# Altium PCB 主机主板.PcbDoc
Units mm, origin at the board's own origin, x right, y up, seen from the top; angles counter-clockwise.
Board outline 20.02 x 52.05 mm, 2 copper layers (Top Layer, Bottom Layer), stack 1.793 mm thick; 21 components, 30 nets, 89 pads, 104 vias.
Unrouted connection lines stored in the file: 27.
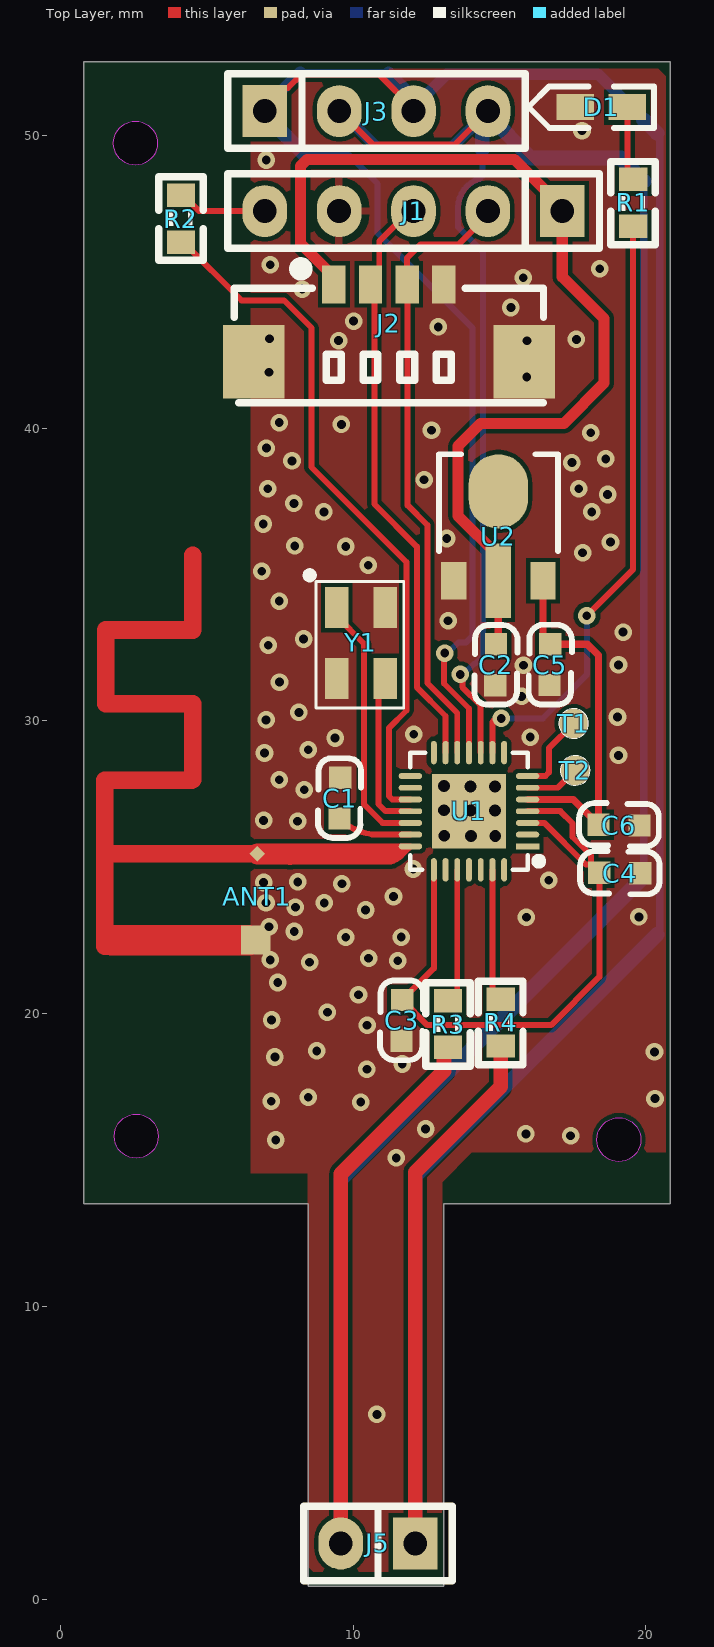
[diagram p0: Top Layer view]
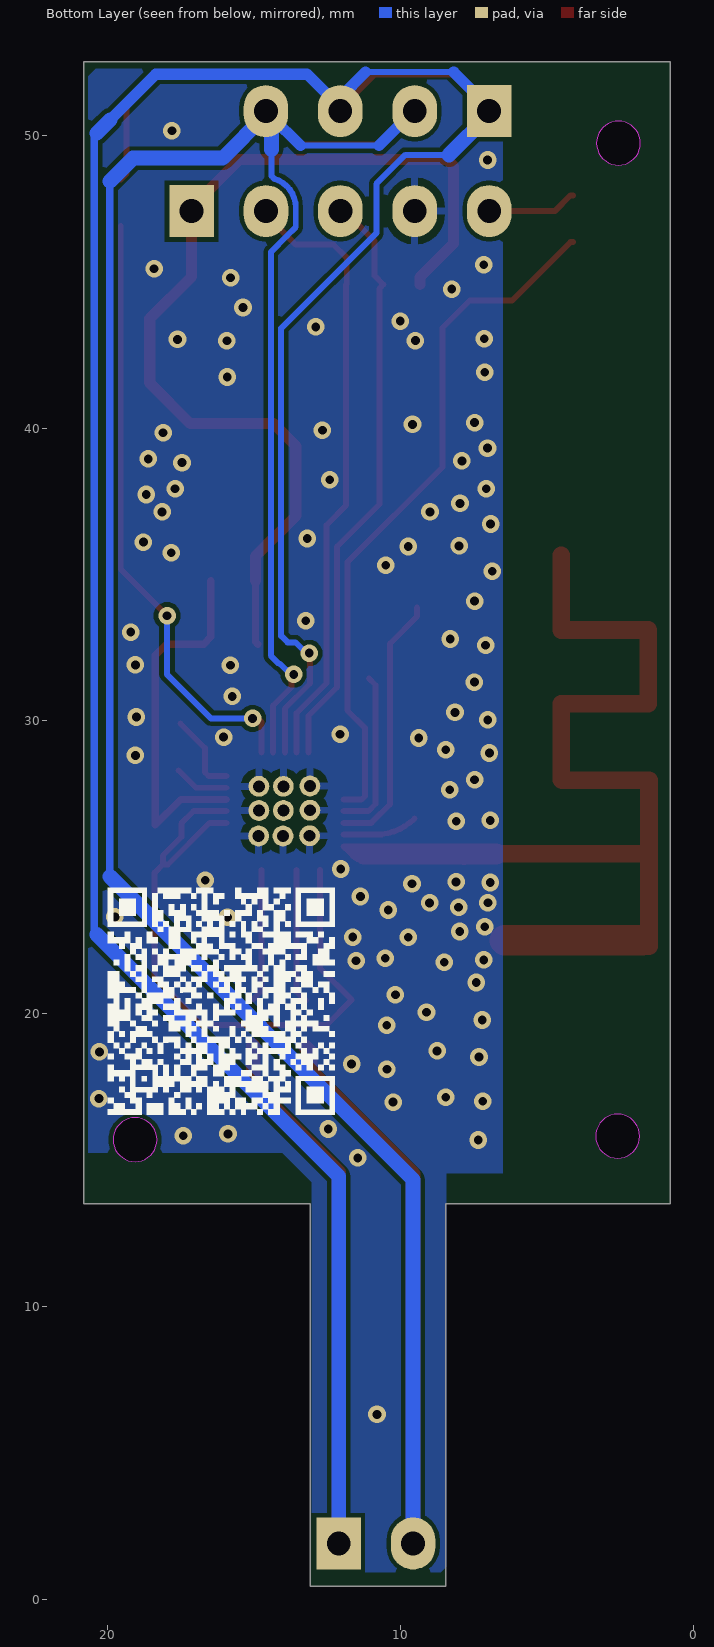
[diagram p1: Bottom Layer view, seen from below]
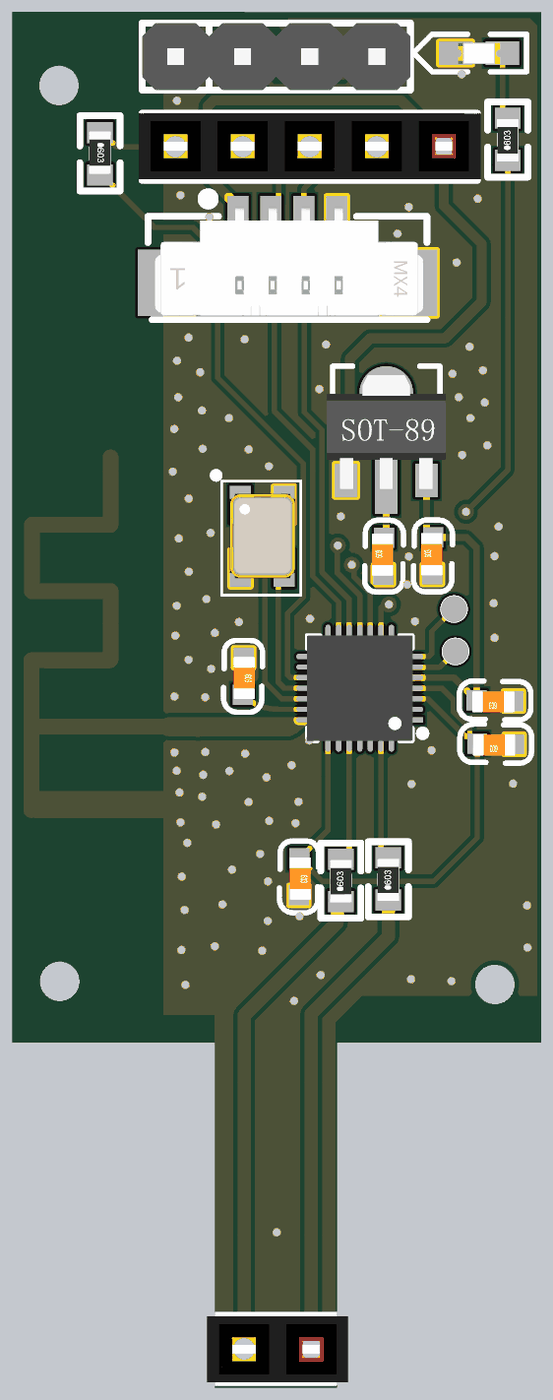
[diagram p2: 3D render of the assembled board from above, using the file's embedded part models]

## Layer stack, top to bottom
Top Solder: solder mask 0.0102, Solder Resist, Dk 3.5
Top Layer: signal copper 0.0356
Dielectric 2: prepreg 0.0508, FR-4, Dk 4.61
Dielectric 1: prepreg 1.62, FR-4, Dk 4.61
Dielectric 3: prepreg 0.0508, FR-4, Dk 4.61
Bottom Layer: signal copper 0.0356
Bottom Solder: solder mask 0.0102, Solder Resist, Dk 3.5

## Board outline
0.807,13.509 0.807,52.505 0.813,52.502 20.827,52.502 20.827,13.509 13.091,13.509 13.091,0.457 8.476,0.457 8.476,13.509
cut-out: 19.076,14.956 cw(c19.076,15.706) 18.326,15.706 cw(c19.076,15.706) 19.076,16.456 cw(c19.076,15.706) 19.826,15.706 cw(c19.076,15.706)
cut-out: 2.599,15.075 cw(c2.599,15.825) 1.849,15.825 cw(c2.599,15.825) 2.599,16.575 cw(c2.599,15.825) 3.349,15.825 cw(c2.599,15.825)
cut-out: 2.572,48.975 cw(c2.572,49.725) 1.822,49.725 cw(c2.572,49.725) 2.572,50.475 cw(c2.572,49.725) 3.322,49.725 cw(c2.572,49.725)

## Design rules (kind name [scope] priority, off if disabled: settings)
Clearance [All] p1: gap=0.152 ignorepadtopadclearanceinfootprint=FALSE
Height [All] p1: minheight=0 maxheight=254 prefheight=12.7
HoleSize [All] p1: absolutevalues=TRUE maxlimit=5.08 minlimit=0.025 maxpercent=80.000 minpercent=20.000
HoleToHoleClearance [All] p1: gap=0.36 allowstackedmicrovias=TRUE
MinimumSolderMaskSliver [All] p1: minsoldermaskwidth=0
PlaneConnect [All] p1: planeconnectstyle=Relief reliefexpansion=0.254 reliefentries=4 reliefconductorwidth=0.102 reliefairgap=0.127
PolygonConnect PolygonConnect_9 [All vs IsNamedPolygon('Top Layer-GND')] p1: connectstyle=Direct reliefconductorwidth=0.254 reliefentries=4 polygonreliefangle="90 Angle" airgapwidth=0.254
PolygonConnect PolygonConnect_8 [All vs IsNamedPolygon('Bottom Layer-GND')] p2: connectstyle=Direct reliefconductorwidth=0.254 reliefentries=4 polygonreliefangle="90 Angle" airgapwidth=0.254
PolygonConnect PolygonConnect_7 [All vs IsNamedPolygon('Bottom Layer-GND')] p3: thpad.connectstyle=Direct thpad.reliefconductorwidth=0.254 thpad.reliefentries=4 thpad.polygonreliefangle="90 Angle" thpad.airgapwidth=0.254 smdpad.connectstyle=Direct smdpad.reliefconductorwidth=0.254 smdpad.reliefentries=4 smdpad.polygonreliefangle="90 Angle" smdpad.airgapwidth=0.254 via.connectstyle=Relief via.reliefconductorwidth=0.254 via.reliefentries=4 via.polygonreliefangle="90 Angle" via.airgapwidth=0.254
PolygonConnect PolygonConnect_6 [All vs IsNamedPolygon('Top Layer-GND')] p4: thpad.connectstyle=Direct thpad.reliefconductorwidth=0.254 thpad.reliefentries=4 thpad.polygonreliefangle="90 Angle" thpad.airgapwidth=0.254 smdpad.connectstyle=Direct smdpad.reliefconductorwidth=0.254 smdpad.reliefentries=4 smdpad.polygonreliefangle="90 Angle" smdpad.airgapwidth=0.254 via.connectstyle=Relief via.reliefconductorwidth=0.254 via.reliefentries=4 via.polygonreliefangle="90 Angle" via.airgapwidth=0.254
PolygonConnect PolygonConnect_5 [All vs IsNamedPolygon('Top Layer-GND')] p5: thpad.connectstyle=Relief thpad.reliefconductorwidth=0.254 thpad.reliefentries=4 thpad.polygonreliefangle="90 Angle" thpad.airgapwidth=0.254 smdpad.connectstyle=Direct smdpad.reliefconductorwidth=0.254 smdpad.reliefentries=4 smdpad.polygonreliefangle="90 Angle" smdpad.airgapwidth=0.254 via.connectstyle=Relief via.reliefconductorwidth=0.254 via.reliefentries=4 via.polygonreliefangle="90 Angle" via.airgapwidth=0.254
PolygonConnect PolygonConnect_4 [All vs IsNamedPolygon('NONET_L-01_P-001')] p6: thpad.connectstyle=Relief thpad.reliefconductorwidth=0.254 thpad.reliefentries=4 thpad.polygonreliefangle="90 Angle" thpad.airgapwidth=0.254 smdpad.connectstyle=Direct smdpad.reliefconductorwidth=0.254 smdpad.reliefentries=4 smdpad.polygonreliefangle="90 Angle" smdpad.airgapwidth=0.254 via.connectstyle=Direct via.reliefconductorwidth=0.254 via.reliefentries=4 via.polygonreliefangle="90 Angle" via.airgapwidth=0.254
PolygonConnect PolygonConnect_3 [All vs IsNamedPolygon('NONET_L-01_P-001')] p7: thpad.connectstyle=Relief thpad.reliefconductorwidth=0.254 thpad.reliefentries=4 thpad.polygonreliefangle="90 Angle" thpad.airgapwidth=0.254 smdpad.connectstyle=Direct smdpad.reliefconductorwidth=0.254 smdpad.reliefentries=4 smdpad.polygonreliefangle="90 Angle" smdpad.airgapwidth=0.254 via.connectstyle=Direct via.reliefconductorwidth=0.254 via.reliefentries=4 via.polygonreliefangle="90 Angle" via.airgapwidth=0.254
PolygonConnect PolygonConnect_2 [All vs IsNamedPolygon('GND_L02_P001')] p8: thpad.connectstyle=Relief thpad.reliefconductorwidth=0.254 thpad.reliefentries=4 thpad.polygonreliefangle="90 Angle" thpad.airgapwidth=0.254 smdpad.connectstyle=Direct smdpad.reliefconductorwidth=0.254 smdpad.reliefentries=4 smdpad.polygonreliefangle="90 Angle" smdpad.airgapwidth=0.254 via.connectstyle=Direct via.reliefconductorwidth=0.254 via.reliefentries=4 via.polygonreliefangle="90 Angle" via.airgapwidth=0.254
PolygonConnect [All vs IsNamedPolygon('GND_L01_P002')] p9: thpad.connectstyle=Relief thpad.reliefconductorwidth=0.254 thpad.reliefentries=4 thpad.polygonreliefangle="90 Angle" thpad.airgapwidth=0.254 smdpad.connectstyle=Direct smdpad.reliefconductorwidth=0.254 smdpad.reliefentries=4 smdpad.polygonreliefangle="90 Angle" smdpad.airgapwidth=0.254 via.connectstyle=Direct via.reliefconductorwidth=0.254 via.reliefentries=4 via.polygonreliefangle="90 Angle" via.airgapwidth=0.254
PolygonConnect PolygonConnect_1 [All] p10: thpad.connectstyle=Relief thpad.reliefconductorwidth=0.254 thpad.reliefentries=4 thpad.polygonreliefangle="90 Angle" thpad.airgapwidth=0.254 smdpad.connectstyle=Relief smdpad.reliefconductorwidth=0.254 smdpad.reliefentries=4 smdpad.polygonreliefangle="90 Angle" smdpad.airgapwidth=0.152 via.connectstyle=Direct via.reliefconductorwidth=0.254 via.reliefentries=4 via.polygonreliefangle="45 Angle" via.airgapwidth=0.254
RoutingVias [All] p1: holewidth=0.3 width=0.3 viastyle="Through Hole" minholewidth=0.3 minwidth=0.3 maxholewidth=0.711 maxwidth=1.27
SilkToSilkClearance [All] p1: silktosilkclearance=0
SilkToSolderMaskClearance [IsPad] p1: minsilkscreentomaskgap=0 clearancetoexposedcopper=TRUE
SolderMaskExpansion [All] p1: expansion=0.102 istentingtop=FALSE
Width [All] p1: maxlimit=127 minlimit=0.076 preferedwidth=0.152
23 further rules are at their usual default settings.

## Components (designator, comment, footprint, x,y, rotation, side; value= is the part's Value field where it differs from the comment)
ANT1 "PCB ANT" ANT_2.4G_Pcb_ESP_C3_7P 6.505,22.566 r270 top
C1 "105" CAP_0603 9.572,27.357 r270 top
C2 "C0603" CAP_0603 14.847,31.924 r90 top value=105
C3 "104" CAP_0603 11.688,19.769 r270 top
C4 "105" CAP_0603 19.099,24.786 r180 top
C5 "105" CAP_0603 16.7,31.931 r90 top
C6 "C0603" CAP_0603 19.073,26.422 r180 top value=105
D1 "LED 正贴蓝灯" LED-0603W 19.364,50.958 r180 top
J1 "Female HDR1X5" Fe-HDR1X5/2.54-S 17.146,47.405 r270 top
J2 "MX1.25-4P" MX1.25S-4P 11.236,42.639 r0 top
J3 "Pin HDR1X4" "Pin HDR1X4/2.54mm-S" 6.988,50.818 r90 top
J5 "Female HDR1X2" Fe-HDR1X2/2.54-S 12.123,1.92 r180 top
R1 "R0603" RES_0603 19.563,47.677 r90 top value=1K
R2 "R0603" RES_0603 4.125,47.157 r270 top value=4.7K
R3 "R0603" RES_0603 13.243,19.64 r90 top value=4.7K
R4 "R0603" RES_0603 15.042,19.688 r90 top value=4.7K
T1 "TP" TEST 17.53,29.912 r0 top
T2 "TP" TEST 17.585,28.309 r0 top
U1 "CH573F" QFN28_4X4 15.959,25.718 r90 top
U2 "MD7530H" SOT89 14.962,34.786 r0 top
Y1 "XTAL3225" XT_3225_4 10.269,32.661 r270 top value="32MHz 10PPM 12PF"

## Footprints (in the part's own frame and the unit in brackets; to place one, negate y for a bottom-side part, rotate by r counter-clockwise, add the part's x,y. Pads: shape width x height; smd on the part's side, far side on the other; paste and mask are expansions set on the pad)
ANT_2.4G_Pcb_ESP_C3_7P [mm] "7P天线"
  rect 0.381x0.381 smd rot 135 paste-50.8 mask+0.102: 1(-2.893,0.227)
  rect 1x1 smd paste-50.8 mask+0.102: 2(0.043,0.172)
  Top Layer lines w0.6: 0.257,-4.977 -0.023,-4.977 ; -0.15,-4.977 -2.893,-4.977 ; -7.991,-1.98 -5.433,-1.98 -5.407,-2.005 -5.408,-4.977 -2.893,-4.977 ; -8.024,-1.98 -8.024,-4.951 -10.538,-4.951 -10.538,-1.98 -13.084,-1.98 ; -2.893,0.227 -2.893,0.194 -2.893,-0.265 -2.893,-4.977
  Top Layer lines w1.032: 0.053,-4.752 0.053,-0.053
CAP_0603 [mil]
  rect 30x30 smd: 1(-27.79,-0.35) 2(27.21,-1.35)
  silkscreen extent -54,-30 53,28, body extent -29,-15 34,17, height 12
Fe-HDR1X2/2.54-S [mil] "Connector; Header; 2x2 Position"
  rect 60x70 hole 32: 1(0,0)
  oval 60x70 hole 32: 2(100,0)
  silkscreen extent -50,-50 150,50, body extent -55,-48 155,50, height 335
Fe-HDR1X5/2.54-S [mil]
  rect 70x60 hole 32: 1(0,0)
  oval 70x60 hole 32: 2(0,-100) 3(0,-200) 4(0,-300) 5(0,-400)
  silkscreen extent -50,-450 50,50, body extent -50,-455 48,55, height 126
LED-0603W [mil]
  rect 50x35 smd: A(0,0.26) K(70,0.26)
  silkscreen extent -36,-28 133,28, body extent 4,-15 66,17, height 24
MX1.25S-4P [mm]
  rect 2.1x2.5 smd: 0(-4.632,-0.381) 0(4.604,-0.381)
  rect 0.8x1.3 smd: 1(-1.889,2.261) 2(-0.639,2.261) 3(0.611,2.261) 4(1.861,2.261)
  silkscreen extent -5.29,-1.78 5.27,2.99, body extent -5.02,-1.63 5.13,2.47, height 4.7
"Pin HDR1X4/2.54mm-S" [mil]
  rect 70x60 hole 32: 1(0,0)
  oval 70x60 hole 32: 2(0,-100) 3(0,-200) 4(0,-300)
  silkscreen extent -50,-350 50,50, body extent -50,-350 50,50, height 336
QFN28_4X4 [mm]
  round 0.711 hole 0.406: 0(0.352,1.937) 0(0.353,1.102) 0(0.362,2.845) 0(1.224,1.946) 0(1.224,1.111) 0(1.233,2.854) 0(2.05,1.946) 0(2.05,1.111) 0(2.059,2.854)
  rect 2.54x2.54 smd: 0(1.2,2)
  rect 0.2x0.8 smd: 1(0,0)
  oval 0.2x0.8 smd: 2(0.4,0) 3(0.8,0) 4(1.2,0) 5(1.6,0) 6(2,0) 7(2.4,0) 15(2.4,4) 16(2,4) 17(1.6,4) 18(1.2,4) 19(0.8,4) 20(0.4,4) 21(0,4)
  oval 0.8x0.2 smd: 8(3.2,0.8) 9(3.2,1.2) 10(3.2,1.6) 11(3.2,2) 12(3.2,2.4) 13(3.2,2.8) 14(3.2,3.2) 22(-0.8,3.2) 23(-0.8,2.8) 24(-0.8,2.4) 25(-0.8,2) 26(-0.8,1.6) 27(-0.8,1.2) 28(-0.8,0.8)
  silkscreen extent -0.8,-0.51 3.2,4, body extent -0.8,0 3.2,4, height 0.55
RES_0603 [mm]
  rect 0.8x0.965 smd: 1(-0.787,0) 2(0.813,0)
  silkscreen extent -1.42,-0.76 1.42,0.76, body extent -0.83,-0.41 0.77,0.41, height 0.45
SOT89 [mil]
  oval 80x100 smd: 2(0,120)
  rect 34x100 smd: A(0,0)
  rect 34x50 smd: K(60,0) R(-60,0)
  silkscreen extent -80,40 80,170, body extent -89,-13 89,156, height 59
TEST [mil]
  round 40 smd: 1(0,0)
  Top Layer pour cut-out: 26.18,0 26.15,1.37 26.04,2.74 25.86,4.1 25.61,5.44 25.29,6.78 24.9,8.09 24.44,9.38 23.92,10.65 23.33,11.89 22.67,13.09 21.96,14.26 21.18,15.39 20.35,16.48 19.46,17.52 18.51,18.51 17.52,19.46 16.48,20.35 15.39,21.18 14.26,21.96 13.09,22.67 11.89,23.33 10.65,23.92 9.38,24.44 8.09,24.9 6.78,25.29 5.44,25.61 4.1,25.86 2.74,26.04 1.37,26.15 0,26.18 -1.37,26.15 -2.74,26.04 -4.1,25.86 -5.44,25.61 -6.78,25.29 -8.09,24.9 -9.38,24.44 -10.65,23.92 -11.89,23.33 -13.09,22.67 -14.26,21.96 -15.39,21.18 -16.48,20.35 -17.52,19.46 -18.51,18.51 -19.46,17.52 -20.35,16.48 -21.18,15.39 -21.96,14.26 -22.67,13.09 -23.33,11.89 -23.92,10.65 -24.44,9.38 -24.9,8.09 -25.29,6.78 -25.61,5.44 -25.86,4.1 -26.04,2.74 -26.15,1.37 -26.18,0 -26.15,-1.37 -26.04,-2.74 -25.86,-4.1 -25.61,-5.44 -25.29,-6.78 -24.9,-8.09 -24.44,-9.38 -23.92,-10.65 -23.33,-11.89 -22.67,-13.09 -21.96,-14.26 -21.18,-15.39 -20.35,-16.48 -19.46,-17.52 -18.51,-18.51 -17.52,-19.46 -16.48,-20.35 -15.39,-21.18 -14.26,-21.96 -13.09,-22.67 -11.89,-23.33 -10.65,-23.92 -9.38,-24.44 -8.09,-24.9 -6.78,-25.29 -5.44,-25.61 -4.1,-25.86 -2.74,-26.04 -1.37,-26.15 0,-26.18 1.37,-26.15 2.74,-26.04 4.1,-25.86 5.44,-25.61 6.78,-25.29 8.09,-24.9 9.38,-24.44 10.65,-23.92 11.89,-23.33 13.09,-22.67 14.26,-21.96 15.39,-21.18 16.48,-20.35 17.52,-19.46 18.51,-18.51 19.46,-17.52 20.35,-16.48 21.18,-15.39 21.96,-14.26 22.67,-13.09 23.33,-11.89 23.92,-10.65 24.44,-9.38 24.9,-8.09 25.29,-6.78 25.61,-5.44 25.86,-4.1 26.04,-2.74 26.15,-1.37 26.18,0
  silkscreen extent -20,-20 20,20
XT_3225_4 [mm]
  rect 1.4x0.8 smd: 1(-1.206,-0.826) 2(1.207,-0.825) 3(1.206,0.826) 4(-1.207,0.825)
  silkscreen extent -2.42,-1.86 2.22,1.46, body extent -1.62,-1.24 1.58,1.26, height 0.61

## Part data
ANT1: library part CON2
C1 C2 C3 C4 C5 C6: library part Cap_0603, "Capacitor"
D1: library part LED
R1 R2 R3 R4: library part Res_0603, "Resistor"
T1 T2: "TP-1mm"
U1: "RISC-V MCU with BLE/USB/ADC/SPI/4*UART"
U2: library part TL431_SMD, "可调基准稳压芯片"
Y1: library part XTAL_3225_4P, "Crystal Oscillator"

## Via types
v1: diameter 0.6, hole 0.3, Top Layer to Bottom Layer, tented both sides, 104 vias

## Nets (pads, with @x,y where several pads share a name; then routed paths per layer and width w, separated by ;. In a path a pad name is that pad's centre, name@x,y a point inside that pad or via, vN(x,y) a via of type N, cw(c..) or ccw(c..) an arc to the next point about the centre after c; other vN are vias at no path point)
+5V: C2.2 J1.1 J2.1 U2.A | length 34.1
  Top Layer w0.254: C2.2 14.962,32.696 U2.A
  Top Layer w0.381: J2.1 9.347,45.15 8.203,46.295 8.203,48.939 8.426,49.162 15.516,49.162 17.146,47.532 J1.1 17.146,45.161 18.573,43.733 18.573,41.535 17.195,40.156 14.356,40.156 13.587,39.387 13.587,37 14.962,35.624 U2.A
ANT: ANT1.1 U1.21 | length 12.1
  Top Layer w0.203: 7.802,25.701 7.819,25.718 U1.21@11.662,25.718 ; 11.161,25.204 ccw(c11.161,25.889) 11.646,25.404 U1.21@11.909,25.667 ; 11.254,25.457 11.394,25.457 ; 11.321,25.385 11.394,25.457 ; 11.394,25.457 11.402,25.457 ; 11.394,25.457 11.438,25.502 cw(c11.959,24.981) 11.468,25.53 ; 11.402,25.457 ccw(c11.402,26.174) U1.21@11.909,25.667 ; 11.402,25.457 11.508,25.564 ; 11.468,25.53 cw(c11.921,25.077) 11.527,25.582 ; 11.468,25.53 cw(c11.959,24.981) 11.508,25.564 ; 11.508,25.564 cw(c11.959,24.981) U1.21 ; 11.508,25.564 11.527,25.582 ; 11.527,25.582 cw(c11.921,25.077) U1.21@11.921,25.718 ; 11.527,25.582 U1.21@11.662,25.718 ; U1.21@11.662,25.718 U1.21@11.921,25.718 ; U1.21@11.909,25.667 U1.21 ; U1.21@11.921,25.718 U1.21
  Top Layer w0.719: ANT1.1 7.829,25.458 7.83,25.457 ; 7.819,25.457 7.83,25.457 ; 11.254,25.457 7.851,25.457 ; 7.83,25.457 7.851,25.457 ; 7.83,25.457 7.851,25.436 7.851,25.457
BOOT: R2.2 U1.17 | length 24
  Top Layer w0.203: R2.2 4.207,46.344 6.198,44.353 7.646,44.353 8.581,43.419 8.581,38.662 11.825,35.418 11.825,30.353 11.221,29.749 11.221,27.437 11.34,27.318 U1.17
GND: ANT1.2 C1.1 C2.1 C3.2 C4.1 C5.1 C6.1 D1.K J1.4 J2.0 J2.4 U1.0 U2.R Y1.2 Y1.4
  other v1: 10.816,6.326 11.474,15.081 7.36,15.692 17.428,15.834 15.902,15.902 12.479,16.068 10.265,16.986 7.207,17.012 20.31,17.106 8.471,17.151 10.475,18.109 11.681,18.287 7.332,18.526 20.293,18.699 8.763,18.735 10.482,19.608 7.221,19.79 9.124,20.054 10.188,20.648 7.429,21.069 8.518,21.762 11.528,21.81 7.174,21.84 10.53,21.897 9.75,22.614 11.643,22.62 7.993,22.812 7.134,22.973 15.919,23.294 19.762,23.307 10.431,23.546 8.031,23.641 9.02,23.788 7.029,23.794 11.382,24.005 9.62,24.439 6.946,24.484 8.114,24.503 16.681,24.564 12.054,24.945 8.108,26.577 6.946,26.602 8.333,27.647 7.482,27.993 19.064,28.823 6.978,28.906 8.471,29.012 9.388,29.417 16.051,29.447 12.075,29.546 7.032,30.036 19.029,30.135 8.151,30.292 15.756,30.838 7.49,31.326 15.819,31.899 19.064,31.912 7.106,32.585 8.311,32.798 19.219,33.034 13.244,33.419 7.482,34.089 6.883,35.112 10.519,35.314 17.838,35.743 9.751,35.954 8.013,35.975 18.791,36.107 13.198,36.228 6.936,36.722 9.006,37.137 18.15,37.137 7.981,37.426 18.691,37.731 7.085,37.927 17.708,37.929 12.428,38.236 17.472,38.82 7.917,38.876 18.625,38.946 7.043,39.313 18.117,39.84 12.679,39.923 9.602,40.122 7.482,40.185 15.929,41.742 7.133,41.906 9.506,42.986 15.939,42.977 17.626,43.025 7.152,43.044 12.908,43.45 10.021,43.651 15.389,44.115 8.264,44.744 15.813,45.127 18.426,45.44 7.172,45.571 7.038,49.151 17.818,50.145
IN+: R3.2 U1.24 | length 4.6
  Top Layer w0.203: R3.2 13.261,20.452 13.559,20.751 U1.24
IN-: R4.2 U1.27 | length 4.5
  Top Layer w0.203: U1.27 14.759,20.784 R4.2
KEY2: U1.25
KEY3: U1.26
KEY5: U1.28
NetD1_A: D1.A R1.2 | length 2.5
  Top Layer w0.203: D1.A 19.364,48.689 R1.2
NetJ1_5: J1.5 R2.1 | length 3.1
  Top Layer w0.203: R2.1 4.207,47.944 4.746,47.405 J1.5
PA4: U1.23
PA8: T2.1 U1.6 | length 1.9
  Top Layer w0.203: U1.6 16.994,27.718 T2.1
PA9: T1.1 U1.7 | length 2.8
  Top Layer w0.203: U1.7 16.569,28.118 16.688,28.237 16.688,29.07 T1.1
PB4: U1.15
PB7: U1.14
PB10: J1.3 J2.2 U1.13 | length 20.2
  Top Layer w0.203: J1.3 11.919,47.405 10.896,46.382 10.896,45.198 J2.2 10.727,44.771 10.727,37.405 12.18,35.952 12.18,31.147 13.159,30.169 U1.13
PB11: J1.2 J2.3 U1.12 | length 21.1
  Top Layer w0.203: U1.12 13.559,30.272 12.536,31.295 12.536,36.688 11.866,37.357 11.866,44.881 J2.3 11.847,45.81 12.3,46.262 13.59,46.262 14.606,47.278 J1.2
PB12: J3.1 J3.3 J5.1 R4.1 U1.11 | length 118.9
  Top Layer w0.203: J3.1 6.988,50.945 7.648,51.606 7.775,51.606 8.231,52.062 10.9,52.062 12.068,50.894 J3.3 ; v1(13.128,32.317) 13.104,32.293 13.104,31.279 13.959,30.424 U1.11
  Top Layer w0.508: J5.1 12.123,14.592 15.042,17.511 R4.1
  Bottom Layer w0.203: J3.1@6.988,50.691 J3.1 J3.1@6.988,50.945 ; 8.197,52.154 11.207,52.154 ; 8.355,49.324 9.849,49.324 10.838,48.335 10.838,46.653 14.085,43.406 14.085,32.903 13.863,32.68 13.599,32.68 13.235,32.317 v1(13.128,32.317) ; J3.3 12.068,50.945 J3.3@12.068,51.293
  Bottom Layer w0.254: 20.381,22.708 20.466,22.793 20.466,49.98 20.381,50.065
  Bottom Layer w0.381: J3.1@6.988,50.945 8.197,52.154 ; 11.207,52.154 J3.3@12.068,51.293 ; J3.3@12.068,50.945 13.201,52.079 18.368,52.079 19.92,50.526
  Bottom Layer w0.508: J3.1@6.988,50.691 8.355,49.324 ; J5.1 12.123,14.449 20.381,22.708 ; 19.92,50.526 20.381,50.065
PB13: J3.2 J3.4 J5.2 R3.1 U1.10 | length 110.6
  Top Layer w0.203: J3.2 9.542,50.818 10.685,49.675 13.465,49.675 J3.4 ; v1(13.658,31.588) 13.734,31.512 13.734,31.152 14.359,30.527 U1.10
  Top Layer w0.508: J5.2 9.583,14.531 13.102,18.05 13.102,18.711 R3.1
  Bottom Layer w0.203: J3.2 J3.2@9.567,50.818 ; 10.745,49.641 13.431,49.641 ; v1(13.658,31.588) 13.766,31.588 14.129,31.951 14.164,31.951 14.441,32.229 14.441,46.006 13.887,46.56 13.59,46.858 13.59,47.278 13.59,47.532 cw(c14.606,47.532) 14.319,48.507 14.354,48.542 14.414,48.602 14.414,49.515 ; J3.4@14.608,50.691 J3.4
  Bottom Layer w0.254: 19.933,24.687 19.933,48.423
  Bottom Layer w0.381: J3.2@9.567,50.818 10.745,49.641 ; 13.431,49.641 J3.4@14.414,50.624
  Bottom Layer w0.508: J5.2 9.583,14.337 19.933,24.687 ; 14.414,49.515 J3.4@14.414,50.624 ; J3.4@14.608,50.691 16.087,49.213 19.143,49.213 19.933,48.423
PB14: R1.1 U1.9 | length 20.9
  Top Layer w0.203: U1.9 14.76,29.969 14.801,30.01 14.985,30.01 v1(15.061,30.086) ; v1(17.982,33.593) 19.563,35.174 R1.1
  Bottom Layer w0.203: v1(15.061,30.086) 16.487,30.086 17.982,31.581 v1(17.982,33.593)
PB15: U1.8
PB23: U1.16
SPK_CTRL: U1.1
SPK_IN: U1.2
VCC: C5.2 C6.2 U1.5 U2.K | length 12.6
  Top Layer w0.254: U1.5 17.52,27.318 C6.2 18.381,32.237 17.996,32.623 C5.2 16.486,32.87 U2.K
VDCIA: C3.1 C4.2 U1.3 U1.4 U1.22 | length 22.7
  Top Layer w0.203: U1.22 12.759,21.554 C3.1 12.54,19.614 16.762,19.614 18.408,21.26 C4.2 C4.2@18.128,25.1 ; U1.3 16.533,26.518 17.951,25.1 C4.2@18.128,25.1 ; U1.4 17.081,26.918 17.495,26.503 17.495,26.037 18.128,25.404 C4.2@18.128,25.1
VINTA: C1.2 U1.20 | length 2.6
  Top Layer w0.203: C1.2 ccw(c10.862,27.99) 10.862,26.118 U1.20
X32MI: U1.19 Y1.1 | length 9
  Top Layer w0.203: Y1.1 9.444,33.568 10.373,32.638 10.373,27.15 11.006,26.518 U1.19
X32MO: U1.18 Y1.3 | length 5.6
  Top Layer w0.203: Y1.3 10.865,31.225 10.865,27.162 11.107,26.919 11.957,26.919 U1.18
pads on no net: U2.2

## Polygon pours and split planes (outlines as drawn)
GND on Bottom Layer "NONET_L-01_P-001" (solid, pour order 2): 6.521,25.098 6.521,25.233 6.521,52.261 20.421,52.261 20.675,52.007 20.675,15.266 14.058,15.266 13.043,14.25 13.043,0.941 8.644,0.941 8.456,1.129 8.456,14.551 6.877,14.551 6.521,14.551
GND on Top Layer "NONET_L-01_P-001" (solid, pour order 1): 6.517,25.104 6.517,25.239 6.517,52.267 20.417,52.267 20.671,52.013 20.671,15.272 14.054,15.272 13.039,14.257 13.039,0.947 8.64,0.947 8.452,1.135 8.452,14.557 6.873,14.557 6.517,14.557

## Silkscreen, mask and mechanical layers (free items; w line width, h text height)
Bottom Overlay:
  drawing of 128 lines, arcs and shapes, not listed
Mechanical 1:
  circle w0.076: c19.076,15.706 r0.75
  circle w0.076: c2.599,15.825 r0.75
  circle w0.076: c2.572,49.725 r0.75
  lines w0.1: 0.807,52.505 0.807,13.509 8.476,13.509 8.476,0.457 13.091,0.457 13.091,13.509 20.827,13.509 20.827,52.502 0.813,52.502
